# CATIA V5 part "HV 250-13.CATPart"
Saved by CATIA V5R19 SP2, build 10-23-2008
Part number: HV 250-13
Bounding box of the stored display mesh (mm): x -18.951 to 18.951, y -18.952 to 18.952, z 0.053 to 94.4
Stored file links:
  C:\Users\Bora\Desktop\3D KATI MODEL- CATIA PART\HV serisi\HV 250\HV 250-13.CATPart
  C:\Program Files\Dassault Systemes\B19\intel_a\reffiles\standard\MetricThickPitch.txt
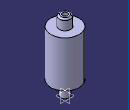
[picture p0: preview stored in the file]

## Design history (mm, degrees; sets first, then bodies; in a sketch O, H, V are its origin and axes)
Body1 (main body)
  Sketch1 on yz-plane, origin (0, 0, 0), H (0, 1, 0), V (0, 0, 1)
    point P1 (7.5, 92.4)
    point P3 (7.5, 92.4)
    point P7 (6, 17)
    point P8 (6, 1)
    point P10 (6, 1)
    point P12 (6, 17)
    line L1 (7.5, 92.4) -> (7.5, 80.4)
    arc A1 centre (5.5, 92.4) radius 2 from (7.5, 92.4) to (5.5, 94.4) ccw
    line L2 (6, 17) -> (6, 1)
    line L3 (5, 0) -> (6, 1)
    arc A2 centre (6, 18) radius 1 from (6, 19) to (6, 17) ccw
    line L4 (0, 0) -> (5, 0)
    line L5 (6, 19) -> (19, 19)
    line L6 (7.5, 80.4) -> (19, 80.4)
    line L7 (5.5, 94.4) -> (0, 94.4)
    point P13 (0, 94.4)
    line L8 (19, 80.4) -> (19, 19)
    horizontal: L4 H, L6 H
    tangency: L5 A2, L7 A1
    coincidence: P13 V, P1 P3, P7 P12, P8 P10
    vertical: L8 V
  Shaft1: profile Sketch1, axis Sketch1.V, angle 360
  Sketch2 on face of Shaft1 from Sketch1.L4, origin (0, 0, 0), H (1, 0, 0), V (0, -1, 0)
    point P1 (0, 0)
  Hole1: placed by Sketch2, at (0, 0, 0) direction (0, 0, 1), diameter 10.106, depth 19, threaded "M12", thread diameter 12, thread depth 19, pitch 1.75
  Sketch3 on face of Shaft1 from Sketch1.L7, origin (0, 0, 94.4), H (1, 0, 0), V (0, 1, 0)
    point P1 (0, 0)
  Hole2: placed by Sketch3, at (0, 0, 94.4) direction (0, 0, -1), diameter 6.647, depth 15, threaded "M8", thread diameter 8, thread depth 15, pitch 1.25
